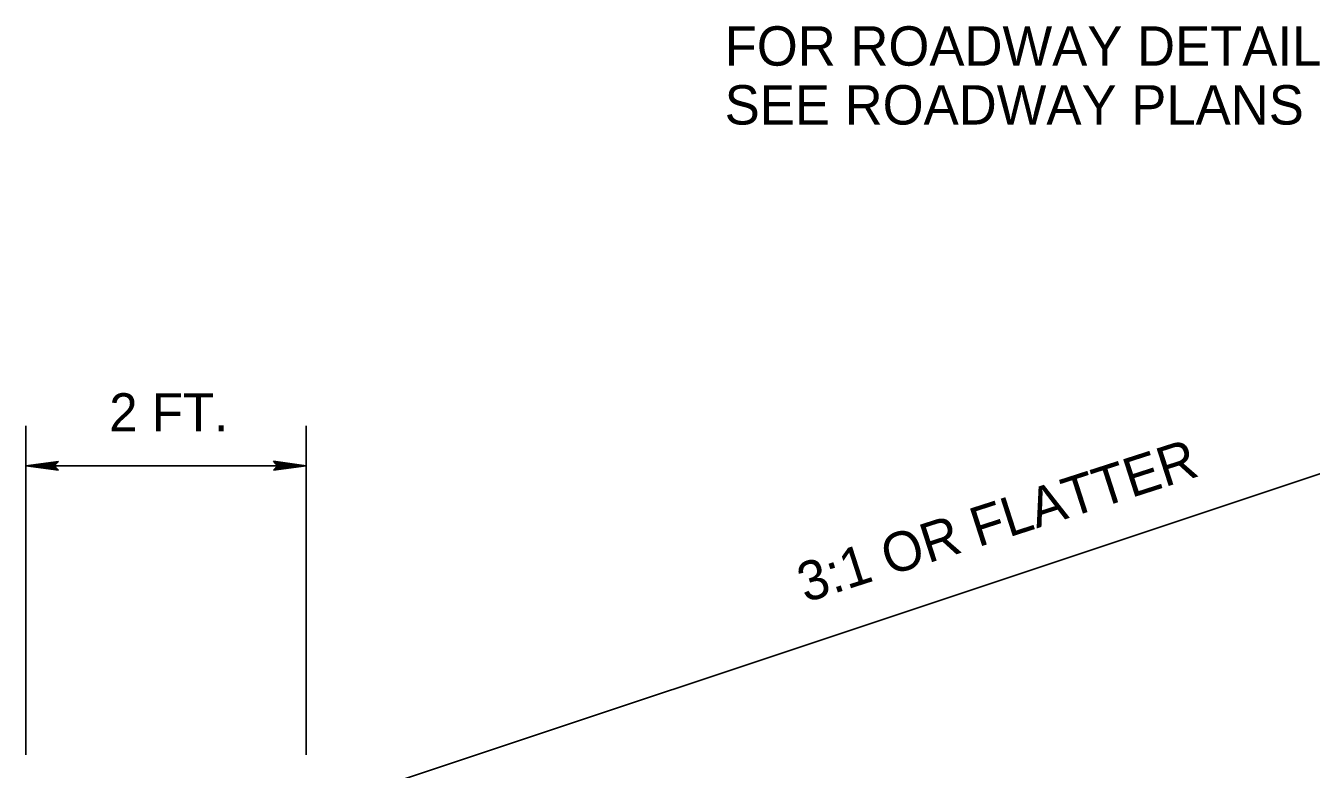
# Model space of a CAD drawing. Extents: x 2189223 to 2190097, y 563994 to 564498.
# Drawn here: x 2189460.4 to 2189546.8, y 564148.6 to 564198.6 of the extents above; entities that cross this region are included whole.
import ezdxf

# ---------------------------------------------------------------- set-up
doc = ezdxf.new("R2010")
doc.units = 0
for name, color, linetype in [('Default', 7, 'Continuous'), ('Misc Plan Tools Cell', 7, 'Continuous'), ('Old_Level_2', 7, 'Continuous')]:
    doc.layers.add(name, color=color, linetype=linetype)

msp = doc.modelspace()

# ---------------------------------------------------------------- linework, layer by layer
at = {"layer": 'Default'}
msp.add_lwpolyline([(2189578.615, 564178.866), (2189478.962, 564145.652)], dxfattribs=at)
at = {"layer": 'Misc Plan Tools Cell'}
for p, q in [((2189460.428, 564171.695), (2189460.428, 564149.592)), ((2189479.278, 564171.699), (2189479.278, 564149.592)), ((2189460.428, 564169.013), (2189462.629, 564169.311)), ((2189462.589, 564169.269), (2189460.428, 564169.013)), ((2189460.428, 564169.013), (2189462.547, 564169.226)), ((2189462.629, 564169.311), (2189462.345, 564169.013)), ((2189479.278, 564169.017), (2189477.077, 564169.313)), ((2189477.36, 564169.017), (2189477.077, 564169.313)), ((2189479.278, 564169.017), (2189477.116, 564169.27)), ((2189477.159, 564169.23), (2189479.278, 564169.017)), ((2189462.507, 564169.184), (2189460.428, 564169.013)), ((2189460.428, 564169.013), (2189462.465, 564169.139)), ((2189462.427, 564169.099), (2189460.428, 564169.013)), ((2189460.428, 564169.013), (2189462.385, 564169.057)), ((2189479.278, 564169.017), (2189460.428, 564169.013)), ((2189460.428, 564169.013), (2189462.629, 564168.717)), ((2189462.345, 564169.013), (2189460.428, 564169.013)), ((2189462.385, 564168.972), (2189460.428, 564169.013)), ((2189460.428, 564169.013), (2189462.427, 564168.929)), ((2189462.465, 564168.887), (2189460.428, 564169.013)), ((2189460.428, 564169.013), (2189462.507, 564168.842)), ((2189462.547, 564168.799), (2189460.428, 564169.013)), ((2189460.428, 564169.013), (2189462.589, 564168.76)), ((2189462.345, 564169.013), (2189462.629, 564168.717)), ((2189479.278, 564169.017), (2189477.077, 564168.718)), ((2189477.077, 564168.718), (2189477.36, 564169.017)), ((2189477.116, 564168.761), (2189479.278, 564169.017)), ((2189479.278, 564169.017), (2189477.159, 564168.803)), ((2189479.278, 564169.017), (2189477.198, 564169.188)), ((2189477.198, 564168.846), (2189479.278, 564169.017)), ((2189477.241, 564169.143), (2189479.278, 564169.017)), ((2189479.278, 564169.017), (2189477.241, 564168.891)), ((2189479.278, 564169.017), (2189477.278, 564169.1)), ((2189477.278, 564168.931), (2189479.278, 564169.017)), ((2189477.321, 564169.058), (2189479.278, 564169.017)), ((2189479.278, 564169.017), (2189477.321, 564168.973)), ((2189477.36, 564169.017), (2189479.278, 564169.017))]:
    msp.add_line(p, q, dxfattribs=at)

# ---------------------------------------------------------------- texts
at = {"layer": 'Default'}
for s, p in [('FOR ROADWAY DETAILS,', (2189507.407, 564195.912)), ('SEE ROADWAY PLANS', (2189507.407, 564191.954))]:
    msp.add_text(s, height=2.64588, dxfattribs=at).set_placement(p)
at = {"layer": 'Misc Plan Tools Cell'}
msp.add_text('2 FT.', height=2.5656, dxfattribs=at).set_placement((2189466.039, 564171.324))
at = {"layer": 'Old_Level_2'}
msp.add_text('3:1 OR FLATTER', height=2.64588, rotation=17.84052, dxfattribs=at).set_placement((2189512.831, 564159.795))

doc.saveas('drawing.dxf')
